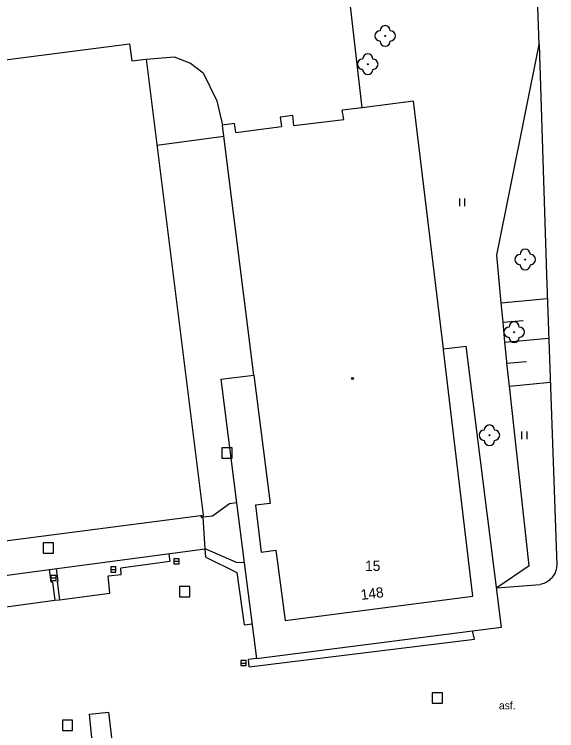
# Model space of a CAD drawing. Extents: x -641829 to -641525, y -1114855 to -1114359.
# Drawn here: x -641705.6 to -641652.8, y -1114670.9 to -1114601.3 of the extents above; entities that cross this region are included whole.
import ezdxf

# ---------------------------------------------------------------- set-up
doc = ezdxf.new("R2010")
doc.units = 0
for name, color, linetype in [('Vrstva 10', 7, 'Continuous'), ('Vrstva 11', 7, 'Continuous'), ('Vrstva 14', 7, 'Continuous'), ('Vrstva 15', 7, 'Continuous'), ('Vrstva 22', 7, 'Continuous'), ('Vrstva 26', 7, 'Continuous'), ('Vrstva 27', 7, 'Continuous'), ('Vrstva 36', 7, 'Continuous'), ('Vrstva 39', 7, 'Continuous'), ('Vrstva 41', 7, 'Continuous'), ('Vrstva 46', 7, 'Continuous'), ('Vrstva 47', 7, 'Continuous'), ('Vrstva 5', 7, 'Continuous'), ('Vrstva 7', 7, 'Continuous')]:
    doc.layers.add(name, color=color, linetype=linetype)

msp = doc.modelspace()

# ---------------------------------------------------------------- linework, layer by layer
at = {"layer": 'Vrstva 10'}
for p, q in [((-641671.74, -1114610.42), (-641674.03, -1114590.7)), ((-641692.76, -1114605.69), (-641690.04, -1114605.49)), ((-641690.04, -1114605.49), (-641688.43, -1114606.1)), ((-641688.43, -1114606.1), (-641687.2, -1114607.02)), ((-641687.2, -1114607.02), (-641685.87, -1114609.75)), ((-641685.87, -1114609.75), (-641685.34, -1114612.1))]:
    msp.add_line(p, q, dxfattribs=at)
at = {"layer": 'Vrstva 11'}
for p, q in [((-641654.56, -1114604.27), (-641655.01, -1114589.6)), ((-641654.56, -1114604.27), (-641653.85, -1114626.63)), ((-641653.85, -1114626.63), (-641652.85, -1114654.85)), ((-641683.96, -1114654.61), (-641687, -1114653.27)), ((-641686.95, -1114654.08), (-641687, -1114653.27)), ((-641690.55, -1114653.75), (-641690.45, -1114654.52)), ((-641686.95, -1114654.08), (-641683.94, -1114655.58)), ((-641690.45, -1114654.52), (-641695.22, -1114655.17)), ((-641683.21, -1114654.63), (-641683.96, -1114654.61)), ((-641652.86, -1114655.03), (-641652.88, -1114655.14)), ((-641652.85, -1114654.91), (-641652.86, -1114655.03)), ((-641652.85, -1114654.85), (-641652.85, -1114654.91)), ((-641701.97, -1114656.52), (-641702.13, -1114655.3)), ((-641701.29, -1114656.42), (-641701.45, -1114655.21)), ((-641696.45, -1114655.9), (-641695.16, -1114655.76)), ((-641695.16, -1114655.76), (-641695.22, -1114655.17)), ((-641683.94, -1114655.58), (-641683.22, -1114660.67)), ((-641653.06, -1114655.71), (-641653.12, -1114655.81)), ((-641653.01, -1114655.6), (-641653.06, -1114655.71)), ((-641652.97, -1114655.49), (-641653.01, -1114655.6)), ((-641652.93, -1114655.38), (-641652.97, -1114655.49)), ((-641652.9, -1114655.26), (-641652.93, -1114655.38)), ((-641652.88, -1114655.14), (-641652.9, -1114655.26)), ((-641701.41, -1114656.44), (-641701.29, -1114656.42)), ((-641701.41, -1114656.44), (-641701.17, -1114658.22)), ((-641696.28, -1114657.59), (-641696.45, -1114655.9)), ((-641653.79, -1114656.49), (-641653.89, -1114656.55)), ((-641653.69, -1114656.42), (-641653.79, -1114656.49)), ((-641653.59, -1114656.35), (-641653.69, -1114656.42)), ((-641653.5, -1114656.27), (-641653.59, -1114656.35)), ((-641653.41, -1114656.19), (-641653.5, -1114656.27)), ((-641653.33, -1114656.1), (-641653.41, -1114656.19)), ((-641653.26, -1114656.01), (-641653.33, -1114656.1)), ((-641653.19, -1114655.91), (-641653.26, -1114656.01)), ((-641653.12, -1114655.81), (-641653.19, -1114655.91)), ((-641701.85, -1114656.51), (-641701.97, -1114656.52)), ((-641701.85, -1114656.51), (-641701.61, -1114658.28)), ((-641658.68, -1114657.08), (-641654.45, -1114656.75)), ((-641654.33, -1114656.72), (-641654.45, -1114656.75)), ((-641654.22, -1114656.69), (-641654.33, -1114656.72)), ((-641654.11, -1114656.65), (-641654.22, -1114656.69)), ((-641654, -1114656.6), (-641654.11, -1114656.65)), ((-641653.89, -1114656.55), (-641654, -1114656.6)), ((-641701.17, -1114658.22), (-641696.28, -1114657.59)), ((-641707.11, -1114659.02), (-641701.61, -1114658.28)), ((-641701.61, -1114658.28), (-641701.17, -1114658.22)), ((-641683.22, -1114660.67), (-641682.45, -1114660.55)), ((-641660.85, -1114662.04), (-641661.02, -1114661.25)), ((-641682.75, -1114664.74), (-641660.85, -1114662.04)), ((-641682.02, -1114663.93), (-641682.81, -1114664.03)), ((-641682.75, -1114664.74), (-641682.81, -1114664.03)), ((-641698.27, -1114669.33), (-641696.38, -1114669.14)), ((-641698.27, -1114669.33), (-641697.94, -1114672.68)), ((-641695.98, -1114672.44), (-641696.38, -1114669.14))]:
    msp.add_line(p, q, dxfattribs=at)
at = {"layer": 'Vrstva 14'}
for p, q in [((-641658.66, -1114624.75), (-641654.56, -1114604.27)), ((-641658.23, -1114629.37), (-641658.66, -1114624.75)), ((-641658.06, -1114631.26), (-641658.23, -1114629.37)), ((-641657.88, -1114633.19), (-641658.06, -1114631.26)), ((-641657.71, -1114635.07), (-641657.88, -1114633.19)), ((-641657.69, -1114635.25), (-641657.71, -1114635.07)), ((-641657.44, -1114637.46), (-641657.69, -1114635.25)), ((-641655.52, -1114654.94), (-641657.44, -1114637.46)), ((-641655.52, -1114654.94), (-641658.68, -1114657.08))]:
    msp.add_line(p, q, dxfattribs=at)
at = {"layer": 'Vrstva 15'}
for p, q in [((-641658.23, -1114629.37), (-641653.76, -1114628.96)), ((-641658.06, -1114631.26), (-641656.11, -1114631.08)), ((-641657.88, -1114633.19), (-641653.63, -1114632.8)), ((-641657.69, -1114635.25), (-641655.78, -1114635.08)), ((-641657.44, -1114637.46), (-641653.48, -1114637.09))]:
    msp.add_line(p, q, dxfattribs=at)
at = {"layer": 'Vrstva 22'}
for centre in [(-641669.52, -1114603.44), (-641671.21, -1114606.19), (-641655.91, -1114625.17), (-641656.98, -1114632.23), (-641659.39, -1114642.24)]:
    msp.add_circle(centre, 0.05, dxfattribs=at)
for centre, start, end in [((-641669.52, -1114602.94), 0, 180), ((-641670.02, -1114603.44), 90, 270), ((-641669.02, -1114603.44), 270, 90), ((-641669.52, -1114603.94), 180, 0), ((-641671.21, -1114605.69), 0, 180), ((-641671.71, -1114606.19), 90, 270), ((-641670.71, -1114606.19), 270, 90), ((-641671.21, -1114606.69), 180, 0), ((-641655.91, -1114624.67), 0, 180), ((-641656.41, -1114625.17), 90, 270), ((-641655.41, -1114625.17), 270, 90), ((-641655.91, -1114625.67), 180, 0), ((-641656.98, -1114631.73), 0, 180), ((-641657.48, -1114632.23), 90, 270), ((-641656.48, -1114632.23), 270, 90), ((-641656.98, -1114632.73), 180, 0), ((-641659.89, -1114642.24), 90, 270), ((-641659.39, -1114641.74), 0, 180), ((-641658.89, -1114642.24), 270, 90), ((-641659.39, -1114642.74), 180, 0)]:
    msp.add_arc(centre, 0.5, start, end, dxfattribs=at)
at = {"layer": 'Vrstva 26'}
for points in [[(-641685.38, -1114644.47), (-641684.38, -1114644.47), (-641684.38, -1114643.47), (-641685.38, -1114643.47)], [(-641702.75, -1114653.69), (-641701.75, -1114653.69), (-641701.75, -1114652.69), (-641702.75, -1114652.69)], [(-641689.51, -1114657.93), (-641688.51, -1114657.93), (-641688.51, -1114656.93), (-641689.51, -1114656.93)], [(-641664.96, -1114668.27), (-641663.96, -1114668.27), (-641663.96, -1114667.27), (-641664.96, -1114667.27)], [(-641700.89, -1114670.94), (-641699.89, -1114670.94), (-641699.89, -1114669.94), (-641700.89, -1114669.94)]]:
    msp.add_lwpolyline(points, close=True, dxfattribs=at)
at = {"layer": 'Vrstva 27'}
for p, q in [((-641690.05, -1114654.49), (-641689.55, -1114654.49)), ((-641696.19, -1114655.28), (-641695.69, -1114655.28)), ((-641702, -1114656.11), (-641701.5, -1114656.11)), ((-641683.53, -1114664.38), (-641683.03, -1114664.38))]:
    msp.add_line(p, q, dxfattribs=at)
for points in [[(-641690.05, -1114654.74), (-641689.55, -1114654.74), (-641689.55, -1114654.24), (-641690.05, -1114654.24)], [(-641696.19, -1114655.53), (-641695.69, -1114655.53), (-641695.69, -1114655.03), (-641696.19, -1114655.03)], [(-641702, -1114656.36), (-641701.5, -1114656.36), (-641701.5, -1114655.86), (-641702, -1114655.86)], [(-641683.53, -1114664.63), (-641683.03, -1114664.63), (-641683.03, -1114664.13), (-641683.53, -1114664.13)]]:
    msp.add_lwpolyline(points, close=True, dxfattribs=at)
at = {"layer": 'Vrstva 36'}
for p, q in [((-641662.274, -1114619.982), (-641662.274, -1114619.234)), ((-641661.774, -1114619.982), (-641661.774, -1114619.234)), ((-641656.234, -1114642.624), (-641656.234, -1114641.872)), ((-641655.734, -1114642.624), (-641655.734, -1114641.872))]:
    msp.add_line(p, q, dxfattribs=at)
at = {"layer": 'Vrstva 39'}
for radius in [0.09, 0.0398]:
    msp.add_circle((-641672.69, -1114636.73), radius, dxfattribs=at)
at = {"layer": 'Vrstva 5'}
for p, q in [((-641722.8, -1114607.87), (-641694.37, -1114604.21)), ((-641694.37, -1114604.21), (-641694.14, -1114605.86)), ((-641694.14, -1114605.86), (-641692.76, -1114605.69)), ((-641692.76, -1114605.69), (-641687.21, -1114650.01)), ((-641666.78, -1114609.78), (-641671.74, -1114610.42)), ((-641663.85, -1114633.86), (-641666.78, -1114609.78)), ((-641671.74, -1114610.42), (-641673.69, -1114610.67)), ((-641678.5, -1114611.19), (-641679.71, -1114611.35)), ((-641678.38, -1114612.14), (-641678.5, -1114611.19)), ((-641673.55, -1114611.56), (-641673.69, -1114610.67)), ((-641679.71, -1114611.35), (-641679.59, -1114612.26)), ((-641678.38, -1114612.14), (-641673.55, -1114611.56)), ((-641684.15, -1114611.95), (-641685.34, -1114612.1)), ((-641685.21, -1114613.17), (-641685.34, -1114612.1)), ((-641684.04, -1114612.84), (-641684.15, -1114611.95)), ((-641684.04, -1114612.84), (-641679.59, -1114612.26)), ((-641682.28, -1114636.39), (-641685.21, -1114613.17)), ((-641663.85, -1114633.86), (-641661.64, -1114633.58)), ((-641663.84, -1114633.94), (-641663.85, -1114633.86)), ((-641660.99, -1114657.89), (-641663.84, -1114633.94)), ((-641658.2, -1114660.89), (-641661.64, -1114633.58)), ((-641685.5, -1114636.8), (-641682.28, -1114636.39)), ((-641685.5, -1114636.8), (-641684.48, -1114644.73)), ((-641682.28, -1114636.39), (-641680.7, -1114648.86)), ((-641684.48, -1114644.73), (-641683.96, -1114648.8)), ((-641683.96, -1114648.8), (-641683.21, -1114654.63)), ((-641680.7, -1114648.86), (-641682.12, -1114649.04)), ((-641682.12, -1114649.04), (-641681.56, -1114653.6)), ((-641729.28, -1114655.46), (-641687.21, -1114650.01)), ((-641687.2, -1114650.21), (-641687.21, -1114650.01)), ((-641687, -1114653.27), (-641687.2, -1114650.21)), ((-641702.13, -1114655.3), (-641687, -1114653.27)), ((-641681.56, -1114653.6), (-641680.13, -1114653.4)), ((-641680.13, -1114653.4), (-641679.24, -1114660.24)), ((-641683.21, -1114654.63), (-641682.02, -1114663.93)), ((-641707.39, -1114656), (-641702.13, -1114655.3)), ((-641679.24, -1114660.24), (-641660.99, -1114657.89)), ((-641682.02, -1114663.93), (-641661.02, -1114661.25)), ((-641661.02, -1114661.25), (-641658.2, -1114660.89))]:
    msp.add_line(p, q, dxfattribs=at)
at = {"layer": 'Vrstva 7'}
for p, q in [((-641691.71, -1114614.06), (-641685.21, -1114613.17)), ((-641683.96, -1114648.8), (-641684.64, -1114648.91)), ((-641684.64, -1114648.91), (-641686.31, -1114650.1)), ((-641687.41, -1114650.04), (-641687.39, -1114650.24)), ((-641687.39, -1114650.24), (-641687.2, -1114650.21)), ((-641686.31, -1114650.1), (-641687.2, -1114650.21))]:
    msp.add_line(p, q, dxfattribs=at)

# ---------------------------------------------------------------- texts
at = {"layer": 'Vrstva 41'}
msp.add_text('asf.', height=0.75, dxfattribs=at).set_placement((-641658.46, -1114668.87))
at = {"layer": 'Vrstva 46'}
msp.add_text('15', height=1, dxfattribs=at).set_placement((-641671.47, -1114655.43))
at = {"layer": 'Vrstva 47'}
msp.add_text('148', height=1, rotation=7.33903, dxfattribs=at).set_placement((-641671.83, -1114658.25))

doc.saveas('drawing.dxf')
